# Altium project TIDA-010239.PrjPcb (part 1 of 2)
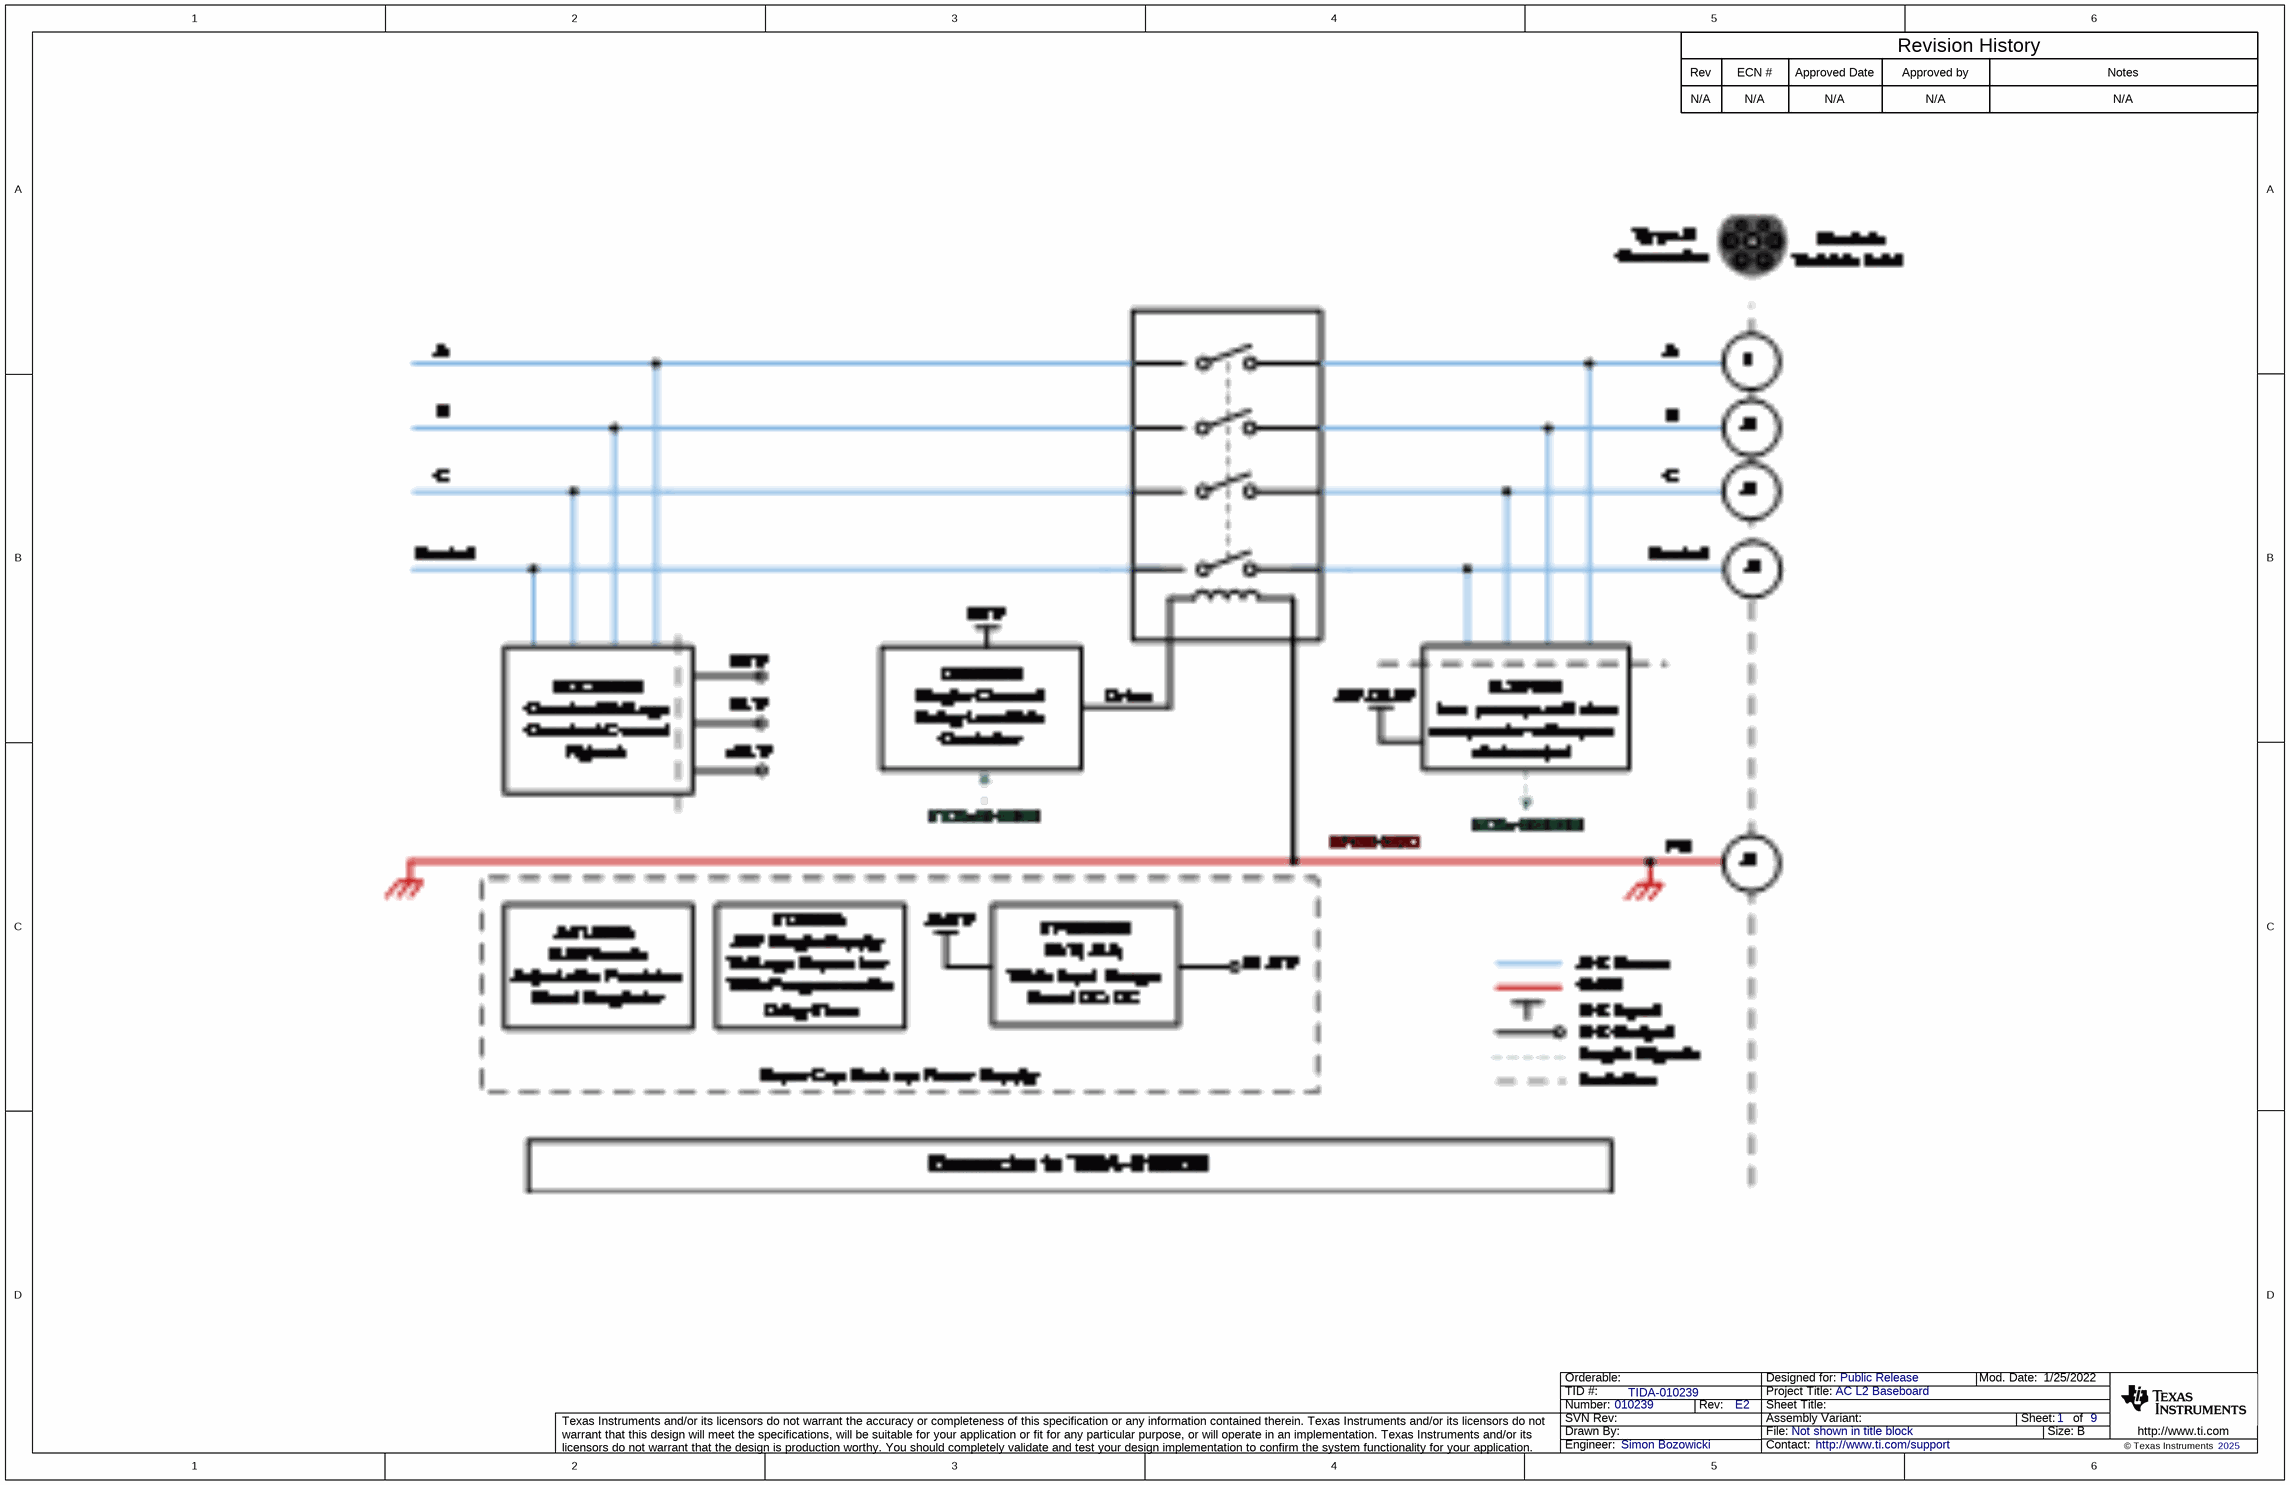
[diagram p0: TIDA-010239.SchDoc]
TID: TIDA-010239; TechSupport: http://www.ti.com/support; SCH_Rev: E2; PRJ_Title: AC L2 Baseboard; PRJ_Number: 010239; PRJ_Engineer: Simon Bozowicki; PRJ_Customer: Public Release; PCB_Rev: E2; PCB_Layout: Rich Chen; CopyrightYear: 2025
9 sheets, 300 parts. Net scope: flat (ports and power ports of the same name join across sheets).
Board file: TIDA-010239.PcbDoc
Sheets:
  TIDA-010239.SchDoc
  TIDA-010239_PWR_Flyback.SchDoc
  TIDA-010239_PWR_Backup.SchDoc
  TIDA-010239_Relay_DRV.SchDoc
  TIDA-010239_Weld_Detection.SchDoc
  TIDA-010239_Weld_Detection_B.SchDoc
  TIDA-010239_HPGP_ZC.SchDoc
  TIDA-010239_Connector.SchDoc
  TIDA-010239_Hardware.SchDoc

## Sheet TIDA-010239.SchDoc
size 431 x 279 mm; Date: Not shown in title block; ApprovedBy: Not shown in title block; CheckedBy: Not shown in title block; Author: Not shown in title block; CompanyName: Not shown in title block; Engineer: Not shown in title block; Organization: Not shown in title block; Address1: Not shown in title block; Address2: Not shown in title block; Address3: Not shown in title block; Address4: Not shown in title block; DocumentNumber: 1; Revision: Use project parameter SCH_Rev; SheetNumber: 1; SheetTotal: 9; PageSetup: Record=PageOptions¦CenterHorizontal=True¦CenterVertical=True¦PrintScale=1.00¦XCorrection=1.00¦YCorrection=1.00¦PrintKind=0¦BorderSize=5000000¦LeftOffset=0¦BottomOffset=0¦Orientation=2¦PaperLength=1000¦PaperWidth=1000¦Scale=100¦PaperSource=15¦PrintQuality=600¦MediaType=1¦DitherType=10¦PaperKind=Letter¦PrintScaleMode=1

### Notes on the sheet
- Rev
- N/A
- ECN #
- Approved Date
- Approved by
- Revision History
- Notes

## Sheet TIDA-010239_PWR_Flyback.SchDoc
size 431 x 279 mm; Date: Not shown in title block; ApprovedBy: Not shown in title block; CheckedBy: Not shown in title block; Author: Not shown in title block; CompanyName: Not shown in title block; Engineer: Not shown in title block; Organization: Not shown in title block; Address1: Not shown in title block; Address2: Not shown in title block; Address3: Not shown in title block; Address4: Not shown in title block; DocumentNumber: 1; Revision: Use project parameter SCH_Rev; SheetNumber: 2; SheetTotal: 9; PageSetup: Record=PageOptions¦CenterHorizontal=True¦CenterVertical=True¦PrintScale=1.00¦XCorrection=1.00¦YCorrection=1.00¦PrintKind=0¦BorderSize=5000000¦LeftOffset=0¦BottomOffset=0¦Orientation=2¦PaperLength=1000¦PaperWidth=1000¦Scale=100¦PaperSource=15¦PrintQuality=600¦MediaType=1¦DitherType=10¦PaperKind=Letter¦PrintScaleMode=1
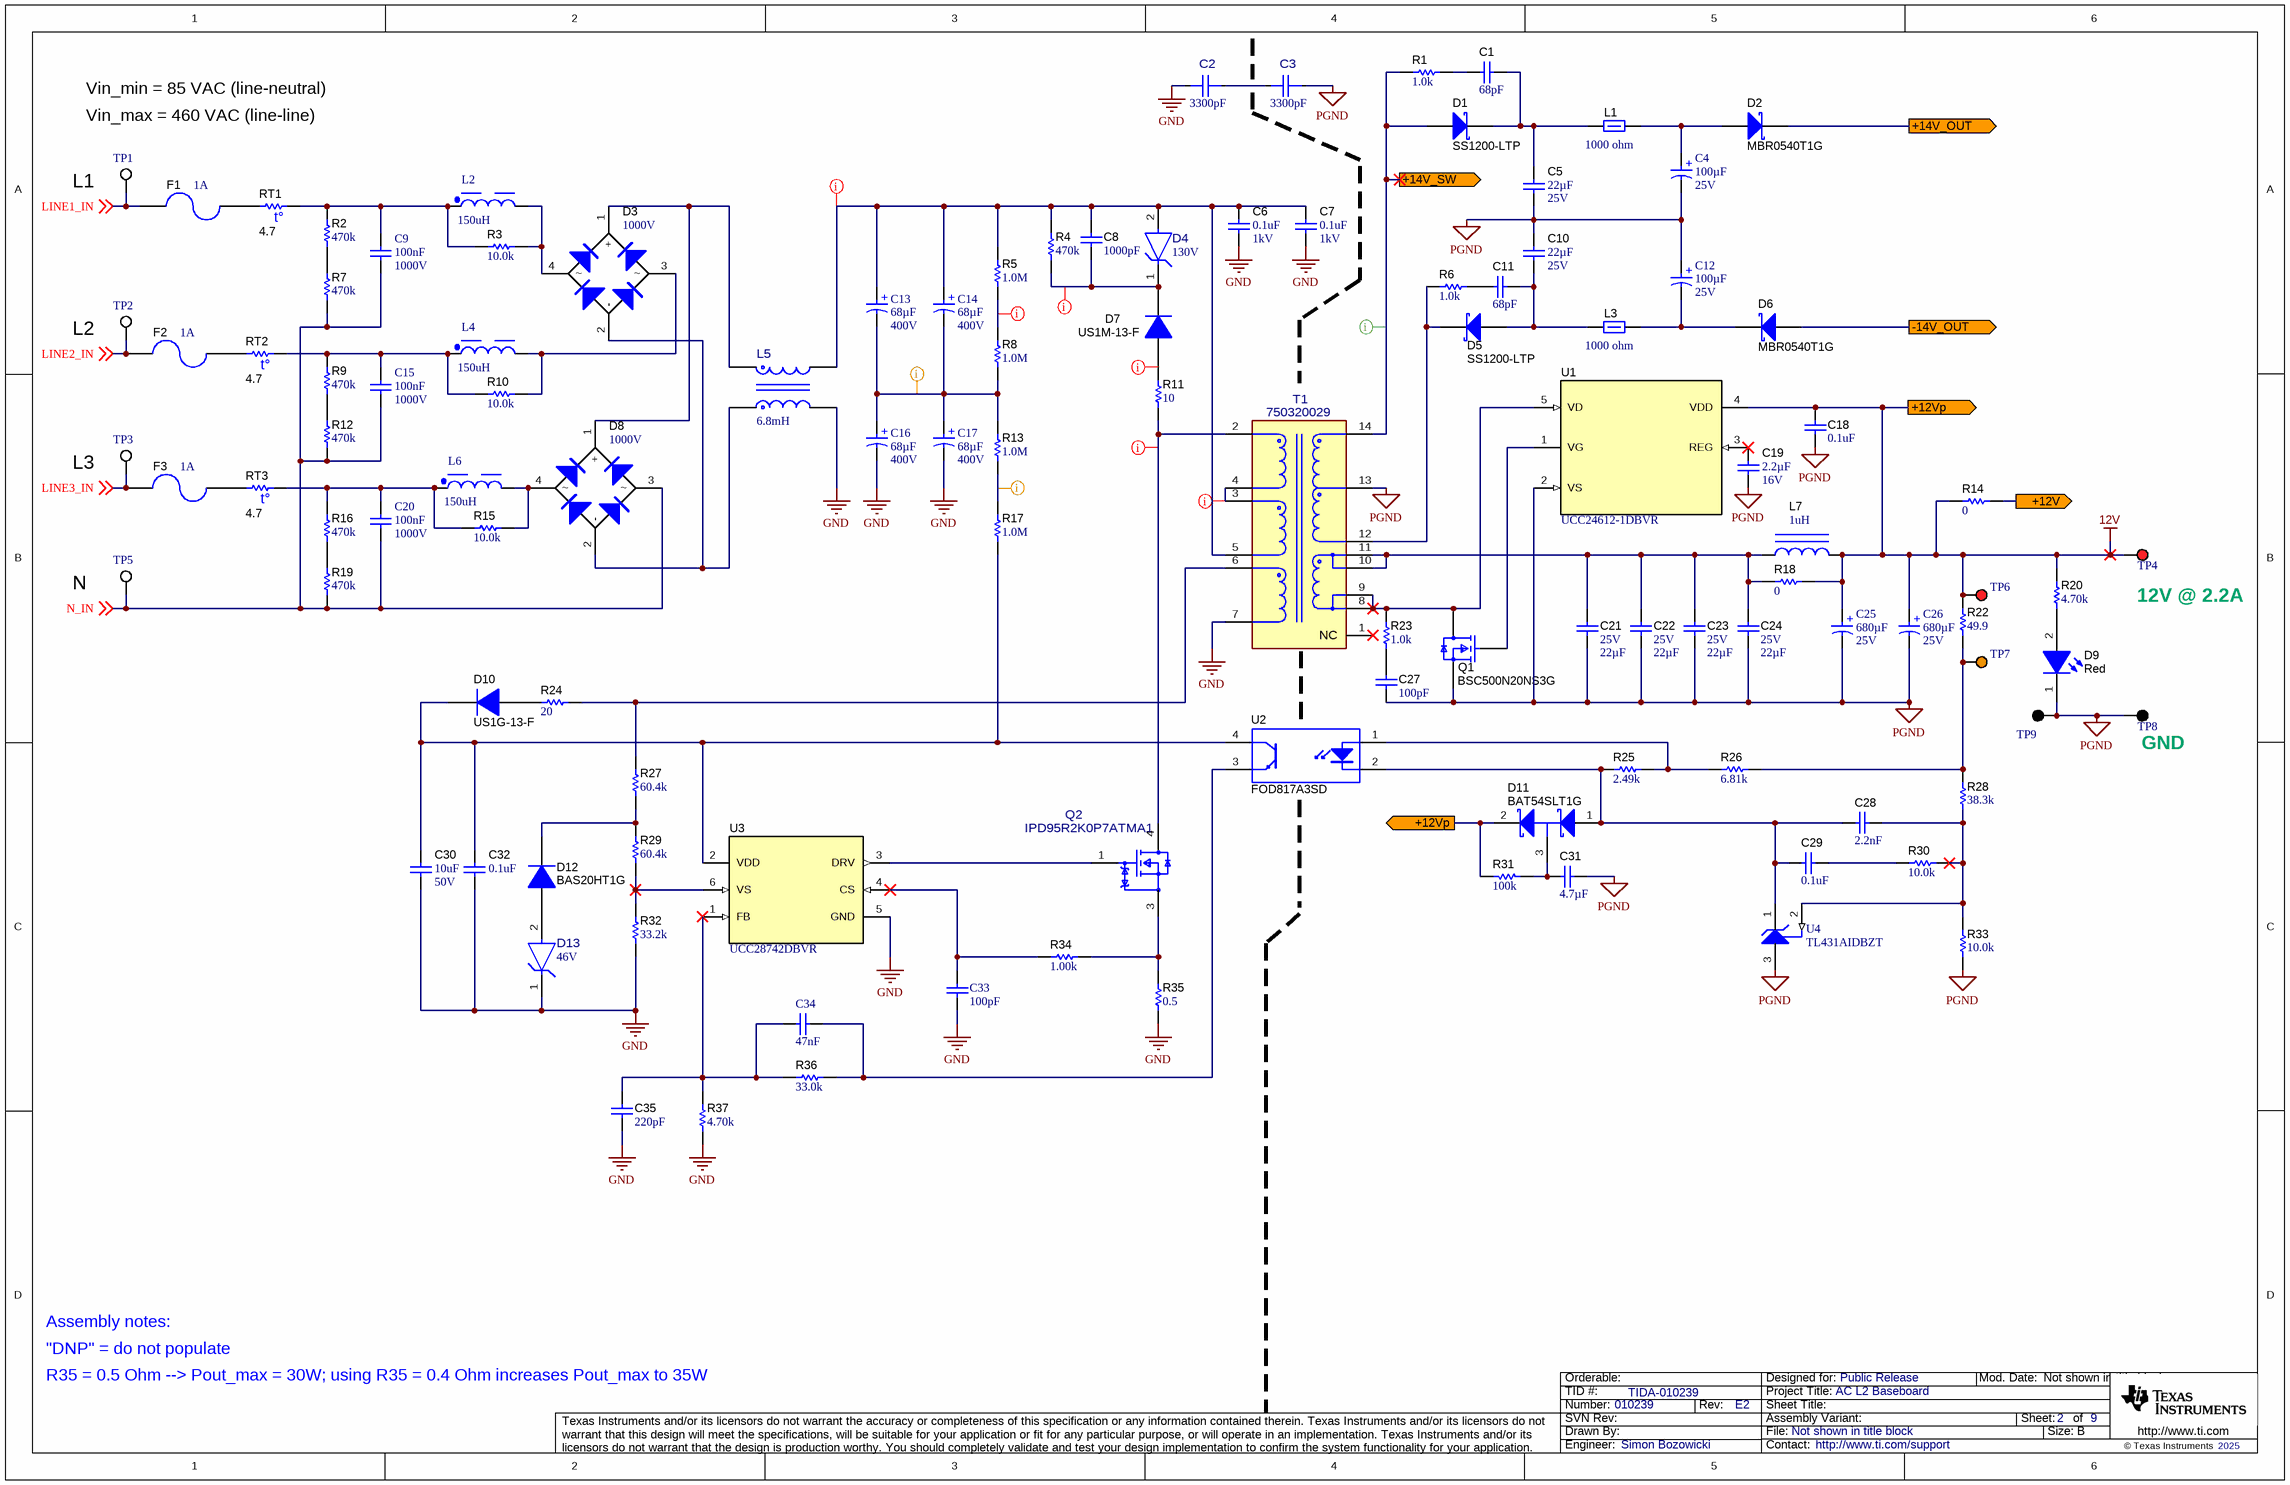
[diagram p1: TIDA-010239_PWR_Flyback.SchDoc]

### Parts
C1  ValueDisplayed: 68pF  [0805_HV]  (hidden comment: GRM21A5C2E680JW01D)
C2  ValueDisplayed: 3300pF  [FP-DE1E3RA332MN4AP01F_RADIAL_CAP_10MM0_5MM0_10MM0-MFG]  (hidden comment: DE1E3RA332MN4AP01F)
C3  ValueDisplayed: 3300pF  [FP-DE1E3RA332MN4AP01F_RADIAL_CAP_10MM0_5MM0_10MM0-MFG]  (hidden comment: DE1E3RA332MN4AP01F)
C4  value 100µF  Rated Voltage (DC): 25V  [WCAP-ATG8_D6.3H11]  (hidden comment: 860010473007)
C5  VDC_V: 25V  ValueDisplayed: 22µF  [1210_270]  (hidden comment: CC1210KKX7R8BB226)
C6  VDC_V: 1kV  ValueDisplayed: 0.1uF  [1812_254]  (hidden comment: C1812W104KDRACTU)
C7  VDC_V: 1kV  ValueDisplayed: 0.1uF  [1812_254]  (hidden comment: C1812W104KDRACTU)
C8  ValueDisplayed: 1000pF  [1206]  (hidden comment: VJ1206Y102KXEAT5Z)
C9  value 100nF  Rated Voltage (DC): 1000V  [WCAP-FTBE_L18W8.5H15]  (hidden comment: 890493425009CS)
C10  VDC_V: 25V  ValueDisplayed: 22µF  [1210_270]  (hidden comment: CC1210KKX7R8BB226)
C11  ValueDisplayed: 68pF  [0805_HV]  (hidden comment: GRM21A5C2E680JW01D)
C12  value 100µF  Rated Voltage (DC): 25V  [WCAP-ATG8_D6.3H11]  (hidden comment: 860010473007)
C13  value 68µF  Rated Voltage (DC): 400V  [WCAP-ATG5_D16H25]  (hidden comment: 860021380017)
C14  value 68µF  Rated Voltage (DC): 400V  [WCAP-ATG5_D16H25]  (hidden comment: 860021380017)
C15  value 100nF  Rated Voltage (DC): 1000V  [WCAP-FTBE_L18W8.5H15]  (hidden comment: 890493425009CS)
C16  value 68µF  Rated Voltage (DC): 400V  [WCAP-ATG5_D16H25]  (hidden comment: 860021380017)
C17  value 68µF  Rated Voltage (DC): 400V  [WCAP-ATG5_D16H25]  (hidden comment: 860021380017)
C18  value 0.1uF  [0603]  (hidden comment: C1608X7R1H104K080AA)
C19  VDC_V: 16V  Cap_F: 2.2µF  [0603]  (hidden comment: GRM188Z71C225KE43)
C20  value 100nF  Rated Voltage (DC): 1000V  [WCAP-FTBE_L18W8.5H15]  (hidden comment: 890493425009CS)
C21  VDC_V: 25V  ValueDisplayed: 22µF  [1210_270]  (hidden comment: CC1210KKX7R8BB226)
C22  VDC_V: 25V  ValueDisplayed: 22µF  [1210_270]  (hidden comment: CC1210KKX7R8BB226)
C23  VDC_V: 25V  ValueDisplayed: 22µF  [1210_270]  (hidden comment: CC1210KKX7R8BB226)
C24  VDC_V: 25V  ValueDisplayed: 22µF  [1210_270]  (hidden comment: CC1210KKX7R8BB226)
C25  value 680µF  Rated Voltage (DC): 25V  [WCAP-ATUL_D10H20]  (hidden comment: 860040475009)
C26  value 680µF  Rated Voltage (DC): 25V  [WCAP-ATUL_D10H20]  (hidden comment: 860040475009)
C27  ValueDisplayed: 100pF  [0805_HV]  (hidden comment: GRM21A5C2E101JW01D)
C28  Cap_F: 2.2nF  [0603]  (hidden comment: C0603C222K5RAC)
C29  value 0.1uF  [0603]  (hidden comment: C1608X7R1H104K080AA)
C30  VDC_V: 50V  ValueDisplayed: 10uF  [1206_180]  (hidden comment: CL31B106KBHNNNE)
C31  Cap_F: 4.7µF  [0805_HV]  (hidden comment: C2012X7R1E475K125AB)
C32  value 0.1uF  [0603]  (hidden comment: C1608X7R1H104K080AA)
C33  value 100pF  [WCAP-CSGP_0603_L1.6W0.8H0.8_Reflow]  (hidden comment: 885012006057)
C34  value 47nF  [WCAP-CSGP_0603_L1.6W0.8H0.8_Reflow]  (hidden comment: 885012206093)
C35  ValueDisplayed: 220pF  [0603]  (hidden comment: C0603C221J5GACTU)
D1  SS1200-LTP  [SMA]
D2  MBR0540T1G  [SOD-123]
D3  value 1000V  [TBS4]  (hidden comment: TBS22M-TP)
D4  VRWM: 130V  [FP-SMCJ130A_DO-214AB-MFG]  (hidden comment: SMCJ130A)
D5  SS1200-LTP  [SMA]
D6  MBR0540T1G  [SOD-123]
D7  US1M-13-F  [SMA]
D8  value 1000V  [TBS4]  (hidden comment: TBS22M-TP)
D9  value Red  [WL_SMCW_RED_1206]  (hidden comment: 150120RS75000)
D10  US1G-13-F  [SMA]
D11  BAT54SLT1G  [SOT-23]
D12  BAS20HT1G  [SOD-323]
D13  Vf_V: 46V  [FP-BZX384C43-E3-08_SOD323-MFG]  (hidden comment: BZX384C43-E3-08)
F1  Irating_A: 1A  [FUSE_0443]  (hidden comment: 0443001.DR)
F2  Irating_A: 1A  [FUSE_0443]  (hidden comment: 0443001.DR)
F3  Irating_A: 1A  [FUSE_0443]  (hidden comment: 0443001.DR)
L1  value 1000 ohm  [0805_HV]  (hidden comment: 74279205)
L2  value 150uH  [WE-TI_1014]  (hidden comment: 7447480151)
L3  value 1000 ohm  [0805_HV]  (hidden comment: 74279205)
L4  value 150uH  [WE-TI_1014]  (hidden comment: 7447480151)
L5  value 6.8mH  [FP-7446121007_PTH_CMC_18MM5_13MM5-MFG]  (hidden comment: 7446121007)
L6  value 150uH  [WE-TI_1014]  (hidden comment: 7447480151)
L7  ValueDisplayed: 1uH  [WE-PD2-S]  (hidden comment: 7447730)
Q1  BSC500N20NS3G  [FP-BSC220N20NSFDATMA1_TSON-8-MFG]
Q2  IPD95R2K0P7ATMA1  [FP-IPD95R2K0P7ATMA1_DPAK-MFG]
R1  ValueDisplayed: 1.0k  [0805_HV]  (hidden comment: ERJ-6GEYJ102V)
R2  ValueDisplayed: 470k  [1206]  (hidden comment: CRCW1206470KJNEA)
R3  ValueDisplayed: 10.0k  [0805_HV]  (hidden comment: CRCW080510K0FKEA)
R4  ValueDisplayed: 470k  [1206]  (hidden comment: CRCW1206470KJNEA)
R5  ValueDisplayed: 1.0M  [1206]  (hidden comment: CRCW12061M00JNEA)
R6  ValueDisplayed: 1.0k  [0805_HV]  (hidden comment: ERJ-6GEYJ102V)
R7  ValueDisplayed: 470k  [1206]  (hidden comment: CRCW1206470KJNEA)
R8  ValueDisplayed: 1.0M  [1206]  (hidden comment: CRCW12061M00JNEA)
R9  ValueDisplayed: 470k  [1206]  (hidden comment: CRCW1206470KJNEA)
R10  ValueDisplayed: 10.0k  [0805_HV]  (hidden comment: CRCW080510K0FKEA)
R11  ValueDisplayed: 10  [1206]  (hidden comment: CRCW120610R0JNEA)
R12  ValueDisplayed: 470k  [1206]  (hidden comment: CRCW1206470KJNEA)
R13  ValueDisplayed: 1.0M  [1206]  (hidden comment: CRCW12061M00JNEA)
R14  ValueDisplayed: 0  [1206]  (hidden comment: RC1206JR-070RL)
R15  ValueDisplayed: 10.0k  [0805_HV]  (hidden comment: CRCW080510K0FKEA)
R16  ValueDisplayed: 470k  [1206]  (hidden comment: CRCW1206470KJNEA)
R17  ValueDisplayed: 1.0M  [1206]  (hidden comment: CRCW12061M00JNEA)
R18  ValueDisplayed: 0  [1206]  (hidden comment: RC1206JR-070RL)
R19  ValueDisplayed: 470k  [1206]  (hidden comment: CRCW1206470KJNEA)
R20  ValueDisplayed: 4.70k  [0603]  (hidden comment: RC0603FR-074K7L)
R22  ValueDisplayed: 49.9  [0603]  (hidden comment: CRCW060349R9FKEA)
R23  ValueDisplayed: 1.0k  [1206]  (hidden comment: CRCW12061K00JNEA)
R24  ValueDisplayed: 20  [0805_HV]  (hidden comment: CRCW080520R0JNEA)
R25  ValueDisplayed: 2.49k  [0603]  (hidden comment: CRCW06032K49FKEA)
R26  ValueDisplayed: 6.81k  [0603]  (hidden comment: CRCW06036K81FKEA)
R27  ValueDisplayed: 60.4k  [0805_HV]  (hidden comment: ERJ-6ENF6042V)
R28  ValueDisplayed: 38.3k  [0603]  (hidden comment: RC0603FR-0738K3L)
R29  ValueDisplayed: 60.4k  [0805_HV]  (hidden comment: ERJ-6ENF6042V)
R30  ValueDisplayed: 10.0k  [0603]  (hidden comment: RC0603FR-0710KL)
R31  ValueDisplayed: 100k  [0603]  (hidden comment: CRCW0603100KFKEA)
R32  ValueDisplayed: 33.2k  [0603]  (hidden comment: RC0603FR-0733K2L)
R33  ValueDisplayed: 10.0k  [0603]  (hidden comment: RC0603FR-0710KL)
R34  ValueDisplayed: 1.00k  [0603]  (hidden comment: CRCW06031K00FKEA)
R35  ValueDisplayed: 0.5  [2010]  (hidden comment: CSRN2010FKR500)
R36  ValueDisplayed: 33.0k  [0603]  (hidden comment: RC0603FR-0733KL)
R37  ValueDisplayed: 4.70k  [0603]  (hidden comment: RC0603FR-074K7L)
RT1  value 4.7  [S153]  (hidden comment: B57153S0479M051)
RT2  value 4.7  [S153]  (hidden comment: B57153S0479M051)
RT3  value 4.7  [S153]  (hidden comment: B57153S0479M051)
T1  750320029  [FP-750320029_PTH14_32MM25_27MM05-MFG]
TP1  5012  [Keystone5012]  (value not drawn)
TP2  5012  [Keystone5012]  (value not drawn)
TP3  5012  [Keystone5012]  (value not drawn)
TP4  5010  [Keystone5010]  (value not drawn)
TP5  5012  [Keystone5012]  (value not drawn)
TP6  5000  [Keystone5000]  (value not drawn)
TP7  5003  [Keystone5003]  (value not drawn)
TP8  5011  [Keystone5011]  (value not drawn)
TP9  5001  [Keystone5001]  (value not drawn)
U1  UCC24612-1DBVR  [DBV0005A_N]
U2  FOD817A3SD  [N04C]
U3  UCC28742DBVR  [DBV0006A_N]
U4  TL431AIDBZT  [DBZ0003A_N]

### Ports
+12V (out), +12Vp (out), +14V_OUT (out), +14V_SW (out), -14V_OUT (out)

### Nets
12V: C18.1 C25.1(P) C26.1(P) D11.2(K) L7.2 R14.1 R18.2 R20.2 R22.2 R31.1 TP4.1 TP6.1 U1.4(VDD) ; port +12Vp
GND: C2.2 C6.2 C7.2 C16.2(N) C17.2(N) C30.2 C32.2 C33.2 C35.1 D13.1(CATHODE) L5.3 R32.1 R35.1 R37.1 T1.7 U3.5(GND)
PGND: C3.1 C4.2(N) C5.2 C10.1 C12.1(P) C18.2 C19.2 C21.1 C22.1 C23.1 C24.1 C25.2(N) C26.2(N) C27.2 C31.2 D9.1(K) Q1.1-2-3(S) R33.1 T1.13 TP8.1 TP9.1 U1.2(VS) U4.3(ANODE)
+12V: R14.2 ; port +12V
+14V_OUT: D2.1(K) ; port +14V_OUT
+14V_SW: D1.2(A) R1.1 T1.14 ; port +14V_SW
-14V_OUT: D6.2(A) ; port -14V_OUT
LINE1_IN: F1.2 TP1.1 ; off-sheet LINE1_IN
LINE2_IN: F2.2 TP2.1 ; off-sheet LINE2_IN
LINE3_IN: F3.2 TP3.1 ; off-sheet LINE3_IN
N_IN: C9.2 C15.2 C20.2 D8.3 R7.1 R12.1 R19.1 TP5.1 ; off-sheet N_IN
NetC1_1: C1.1 C5.1 D1.1(K) L1.1
NetC1_2: C1.2 R1.2
NetC2_1: C2.1 C3.2
NetC4_1: C4.1(P) D2.2(A) L1.2
NetC6_1: C6.1 C7.1 C8.1 C13.1(P) C14.1(P) D4.2(ANODE) L5.4 R4.2 R5.2 T1.5
NetC8_2: C8.2 D4.1(CATHODE) D7.1(K) R4.1
NetC9_1: C9.1 L2.1 R2.2 R3.1 RT1.2
NetC10_2: C10.2 C11.1 D5.2(A) L3.1
NetC11_2: C11.2 R6.2
NetC12_2: C12.2(N) D6.1(K) L3.2
NetC13_2: C13.2(N) C14.2(N) C16.1(P) C17.1(P) R8.1 R13.2
NetC15_1: C15.1 L4.1 R9.2 R10.1 RT2.2
NetC19_1: C19.1 U1.3(REG)
NetC20_1: C20.1 L6.1 R15.1 R16.2 RT3.2
NetC21_2: C21.2 C22.2 C23.2 C24.2 L7.1 R18.1 T1.10 T1.11
NetC27_1: C27.1 R23.1
NetC28_1: C28.1 C29.1 D11.1(A) R25.2 U2.2(K) U4.1(CATHODE)
NetC28_2: C28.2 R28.1 R30.2 R33.2 U4.2(REF)
NetC29_2: C29.2 R30.1
NetC30_1: C30.1 C32.1 D10.1(K) R17.1 U2.4(C) U3.2(VDD)
NetC31_1: C31.1 D11.3(C) R31.2
NetC33_1: C33.1 R34.1 U3.4(CS)
NetC34_1: C34.1 R36.2 U2.3(E)
NetC34_2: C34.2 C35.2 R36.1 R37.2 U3.1(FB)
NetD3_1: D3.1(+) D8.1(+) L5.1
NetD3_2: D3.2(-) D8.2(-) L5.2
NetD3_3: D3.3 L4.2 R10.2
NetD3_4: D3.4 L2.2 R3.2
NetD5_1: D5.1(K) R6.1 T1.12
NetD7_2: D7.2(A) R11.2
NetD8_4: D8.4 L6.2 R15.2
NetD9_2: D9.2(A) R20.1
NetD10_2: D10.2(A) R24.1
NetD12_1: D12.1(K) R27.1 R29.2
NetD12_2: D12.2(A) D13.2(ANODE)
NetF1_1: F1.1 RT1.1
NetF2_1: F2.1 RT2.1
NetF3_1: F3.1 RT3.1
NetQ1_4: Q1.4(G) U1.1(VG)
NetQ1_5-6-7-8: Q1.5-6-7-8(D) R23.2 T1.8 T1.9 U1.5(VD)
NetQ2_1: Q2.1(Gate) U3.3(DRV)
NetQ2_3: Q2.3(Source) R34.2 R35.2
NetQ2_4: Q2.4(Drain) R11.1 T1.2
NetR2_1: R2.1 R7.2
NetR5_1: R5.1 R8.2
NetR9_1: R9.1 R12.2
NetR13_1: R13.1 R17.2
NetR16_1: R16.1 R19.2
NetR22_1: R22.1 R26.2 R28.2 TP7.1
NetR24_2: R24.2 R27.2 T1.6
NetR25_1: R25.1 R26.1 U2.1(A)
NetR29_1: R29.1 R32.2 U3.6(VS)
NetT1_3: T1.3 T1.4

Not connected (* = marked no-connect by the designer): T1 1(NC)*

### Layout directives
rule Clearance Constraint [Clearance = 40mil]: NetC6_1, NetC8_2, NetD7_2, NetQ2_4, NetR5_1, NetT1_3
rule Clearance Constraint [Clearance = 20mil]: NetC13_2, NetR13_1
rule Clearance Constraint [Clearance = 10mil]: +14V_SW

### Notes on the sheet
- Vin_min = 85 VAC (line-neutral)
- Vin_max = 460 VAC (line-line)
- (near TP1) L1
- (near TP2) L2
- (near TP3) L3
- (near TP5) N
- (near TP4) 12V @ 2.2A
- (near TP8) GND
- Assembly notes:
- "DNP" = do not populate
- R35 = 0.5 Ohm --> Pout_max = 30W; using R35 = 0.4 Ohm increases Pout_max to 35W

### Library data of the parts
C1 C11 = CMP-0008246-2: CAP, CERM, 68 pF, 250 V, +/- 5%, C0G/NP0, 0805; Manufacturer: MuRata; TaMin_C: -55°C; Polarized: N; SizeAreaWB_mm2: 6.75; Value1: Unknown; U/M: EA; Value: 68pF; TaMax_C: 125°C; SizeZ_mm: 1.45; SizeX_mm: 2; SizeY_mm: 1.25; Cap_Case: 0805; Value2: 250V; SizeArea_mm2: 2.5; AEC Category: Q200
C2 C3 = CMP-0127096-1: Cap Ceramic Disc 3300pF 20% 300VAC Thru-Hole 10.0x5.0x10.0 Ammo pack; Manufacturer: Murata; AEC Qualified: No; Cap_F: 3.3nF; SizeZ_mm: 13mm; TempCo: +20/-55%; VAC: 300V; Temperature Characteristic: E; Value: 3.3nF; Voltage Ac Rating X: 440V
C4 C12 = CMP-0116473-1: WCAP-ATG8 Aluminum Electrolytic Capacitor, Radial, THT, D6.3 x H11mm, 100uF, 25V; Manufacturer: Wurth Elektronik; Capacitance Tolerance: +/-20%; Dissipation Factor: 14%; Endurance: 2000h; Leakage Current: 25uA; Ripple Current: 209mA; Technical Reference: ATBD110101M025DSPA4B000
C5 C10 C21-C24 = CMP-0082267-1: CAP, CERM, 22 µF, 25 V,+/- 10%, X7R, 1210; Manufacturer: Yageo; TaMin_C: -55°C; ESR_ohm: 1m; Polarized: N; SizeAreaWB_mm2: 14.7; Value1: 0.001 ohm; U/M: EA; Value: 22uF; TaMax_C: 125°C; SizeZ_mm: 2.7; SizeX_mm: 3.2; SizeY_mm: 2.5; Cap_Case: 1210; SizeArea_mm2: 8; AEC Category: Q200
C6 C7 = CMP-0009326-2: CAP, CERM, 0.1 uF, 1000 V, +/- 10%, X7R, 1812; Manufacturer: Kemet; TaMin_C: -55°C; Polarized: N; SizeAreaWB_mm2: 23.1; Value1: Unknown; U/M: EA; Value: 0.1uF; TaMax_C: 125°C; SizeZ_mm: 2.54; SizeX_mm: 4.5; SizeY_mm: 3.2; Cap_Case: 1812; Value2: 1000V; SizeArea_mm2: 14.4; Cap_F: 100nF; AEC Category: Q200
C8 = CMP-0009039-2: CAP, CERM, 1000 pF, 500 V, +/- 10%, X7R, 1206; Manufacturer: Vishay-Vitramon; TaMin_C: -55°C; Polarized: N; SizeAreaWB_mm2: 10.92; Value1: Unknown; U/M: EA; Value: 1000pF; TaMax_C: 125°C; SizeZ_mm: 1.35; SizeX_mm: 3.2; SizeY_mm: 1.6; Value2: 500V; SizeArea_mm2: 5.12; Cap_F: 1nF; AEC Category: Q200
C9 C15 C20 = CMP-0105615-1: WCAP-FTBE Film Capacitor, THT, L18 x W8.5 x H15mm, 100nF, 1000V; Manufacturer: Wurth Elektronik; Capacitance Tolerance: +/-10%; Technical Reference: MPSP015104KA00DCPP45004; Dissipation Factor @100kHz: 2.5%; Dissipation Factor @10kHz: 1.4%; Dissipation Factor @1kHz: 1%; Insulation Resistance: 9000MOhm; Pitch: 15mm; Rate of Voltage Rise: 44V/us
C13 C14 C16 C17 = CMP-0102466-1: WCAP-ATG5 Aluminum Electrolytic Capacitor, Radial, THT, D16 x H25mm, 68µF, 400V; Manufacturer: Wurth Elektronik; Capacitance Tolerance: +/-20%; Dissipation Factor: 15%; Endurance: 2000h; Leakage Current: 816uA; Ripple Current: 410mA; Technical Reference: ATJK250680M400DSPAEB000
C18 C29 C32 = CMP-0007044-5: CAP, CERM, 0.1 uF, 50 V, +/- 10%, X7R, 0603; Manufacturer: TDK; TaMin_C: -55°C; ESR_ohm: 29.6m; Polarized: N; SizeAreaWB_mm2: 4.68; Value1: 0.0296 ohm; U/M: EA; TaMax_C: 125°C; SizeZ_mm: 1; SizeX_mm: 1.6; SizeY_mm: 0.8; Value2: 50V; SizeArea_mm2: 1.28; Cap_F: 100nF; IRMS_A: 971.99mA; AEC Category: Q200
C19 = CMP-0007499-4: CAP, CERM, 2.2 uF, 16 V, +/- 10%, X7R, 0603; Manufacturer: MuRata; TaMin_C: -55°C; Polarized: N; SizeAreaWB_mm2: 4.68; Value1: Unknown; U/M: EA; Value: 2.2uF; TaMax_C: 125°C; SizeZ_mm: 1; SizeX_mm: 1.6; SizeY_mm: 0.8; SizeArea_mm2: 1.28; AEC Category: Q200
C25 C26 = CMP-0116844-1: WCAP-ATUL Aluminum Electrolytic Capacitor, Radial, THT, D10 x H20mm, 680µF, 25V; Manufacturer: Wurth Elektronik; Capacitance Tolerance: 20%; Dissipation Factor: 14%; Endurance: 7000h; Leakage Current: 170uA; Ripple Current: 1400mA; Technical Reference: ATDF200681M025DSPAAG000
C27 = CMP-0008236-2: CAP, CERM, 100 pF, 250 V, +/- 5%, C0G/NP0, 0805; Manufacturer: MuRata; TaMin_C: -55°C; Polarized: N; SizeAreaWB_mm2: 6.75; Value1: Unknown; U/M: EA; Value: 100pF; TaMax_C: 125°C; SizeZ_mm: 1.45; SizeX_mm: 2; SizeY_mm: 1.25; Cap_Case: 0805; Value2: 250V; SizeArea_mm2: 2.5; AEC Category: Q200
C28 = CMP-0006897-4: CAP, CERM, 2200 pF, 50 V, +/- 10%, X7R, 0603; Manufacturer: Kemet; TaMin_C: -55°C; Polarized: N; SizeAreaWB_mm2: 4.68; Value1: Unknown; U/M: EA; Value: 2200pF; TaMax_C: 125°C; SizeZ_mm: 1; SizeX_mm: 1.6; SizeY_mm: 0.8; Value2: 50V; SizeArea_mm2: 1.28; AEC Category: Q200
C30 = CMP-0008802-2: CAP, CERM, 10 uF, 50 V, +/- 10%, X7R, 1206; Manufacturer: Samsung; TaMin_C: -55°C; Polarized: N; SizeAreaWB_mm2: 10.92; Value1: Unknown; U/M: EA; Value: 10uF; TaMax_C: 125°C; SizeZ_mm: 1.8; SizeX_mm: 3.2; SizeY_mm: 1.6; Cap_Case: 1206; SizeArea_mm2: 5.12; Cap_F: 10µF; AEC Category: Q200
C31 = CMP-0007870-2: CAP, CERM, 4.7 uF, 25 V, +/- 10%, X7R, 0805; Manufacturer: TDK; TaMin_C: -55°C; Polarized: N; SizeAreaWB_mm2: 6.75; Value1: Unknown; U/M: EA; Value: 4.7uF; TaMax_C: 125°C; SizeZ_mm: 1.45; SizeX_mm: 2; SizeY_mm: 1.25; Cap_Case: 0805; Value2: 25V; SizeArea_mm2: 2.5; AEC Category: Q200
C33 = CMP-0118889-1: WCAP-CSGP Multilayer Ceramic Chip Capacitor, General Purpose, size 0603, NP0, 100pF, 50VDC; Manufacturer: Wurth Elektronik; Capacitance Tolerance: +/-5%; Insulation Resistance: 10GOhm; Q Factor: 1000; Rated Voltage (DC): 50V; Technical Reference: NP00603101J050DFCT10000
C34 = CMP-0115476-1: WCAP-CSGP Multilayer Ceramic Chip Capacitor, General Purpose, size 0603, X7R, 47nF, 50VDC; Manufacturer: Wurth Elektronik; Capacitance Tolerance: +/-10%; Dissipation Factor: 3%; Insulation Resistance: 10GOhm; Rated Voltage (DC): 50V; Technical Reference: X7R0603473K050DFCT10000
C35 = CMP-0006893-4: CAP, CERM, 220 pF, 50 V, +/- 5%, C0G/NP0, 0603; Manufacturer: Kemet; TaMin_C: -55°C; Polarized: N; SizeAreaWB_mm2: 4.68; Value1: Unknown; U/M: EA; Value: 220pF; TaMax_C: 125°C; SizeZ_mm: 1; SizeX_mm: 1.6; SizeY_mm: 0.8; Value2: 50V; SizeArea_mm2: 1.28; AEC Category: Q200
D1 D5 = CMP-0028981-2: Diode, Schottky, 200 V, 1 A, SMA; Manufacturer: Micro Commercial Components; TJmax_C: 150°C; SizeArea_mm2: 16.3228; Io_A: 1A; AEC Qualified: N; SizeX_mm: 5.59; SizeZ_mm: 2.87; Vf_V: 920mV; Value: 200V; AEC Category: Q101; Value2: 0.92V; SizeY_mm: 2.92; SizeAreaWB_mm2: 37.3428
D2 D6 = CMP-0028526-2: Diode, Schottky, 40 V, 0.5 A, SOD-123; Manufacturer: ON Semiconductor; Green_REACh: Passed; SizeY_mm: 1.7; Io_A: 500mA; SizeArea_mm2: 6.545; RJC_CperW: 118; Green_Lifecycle: Active; Vr_V: 40V; Vf_V: 510mV; TJmax_C: 150°C; AEC Category: Q101; SizeAreaWB_mm2: 13.095; Value1: 0.5A; SizeZ_mm: 1.35; SizeX_mm: 3.85; Value2: 0.51V; Value: 40V
D3 D8 = CMP-0029252-3: Diode, Switching-Bridge, 1000 V, 2.2 A, 8.25x6.6mm; Manufacturer: Micro Commercial Components; Io_A: 2.2A; SizeAreaWB_mm2: 88.15; Vr_V: 1kV; TJmax_C: 150°C; SizeZ_mm: 1.5; SizeX_mm: 8.25; SizeY_mm: 6.6; Vf_V: 1.1V; SizeArea_mm2: 54.45; AEC Qualified: N; AEC Category: Q101; RJC_CperW: 10
D4 = CMP-0127069-1: 209V Clamp 7.2A Ipp Tvs Diode Surface Mount DO-214AB (SMCJ); Manufacturer: Littelfuse Inc; AEC Qualified: No; SizeZ_mm: 2.62mm; Ppk: 1.5kW; Breakdown Voltage: 144V; Direction: Unidirectional; Number Of Channels: 1; TJmax_C: +150°C
D7 = CMP-0076882-2: Diode, Ultrafast, 1000 V, 1 A, SMA; Manufacturer: Diodes Inc.; SizeAreaWB_mm2: 37.3428; Vr_V: 1kV; SizeArea_mm2: 16.3228; TJmax_C: 150°C; AEC Category: Q101; Value: 1000V; SizeZ_mm: 2.87; Green_REACh: Incomplete; Io_A: 1A; Vf_V: 1.7V; SizeY_mm: 2.92; Green_Lifecycle: Not Set; SizeX_mm: 5.59; RJC_CperW: 30.0
D9 = CMP-0002935-3: LED, Red, SMD; Manufacturer: Wurth Elektronik; Vf_V: 2V; Angle: 140; Value1: 0.072W; Vr_V: 5V; Io_A: 20mA; Tjmax_C: 85°C; Type: AlInGaP; Power_TotalModule: 72mW; Ir_A: 10µA
D10 = CMP-0077026-2: Diode, Ultrafast, 400 V, 1 A, SMA; Manufacturer: Diodes Inc.; Value: 400V; SizeY_mm: 2.92; Value1: 1A; SizeAreaWB_mm2: 37.3428; Value2: 1.3V; TJmax_C: 150°C; Green_REACh: Incomplete; SizeArea_mm2: 16.3228; SizeX_mm: 5.59; SizeZ_mm: 2.87; AEC Category: Q101; Green_Lifecycle: Not Set
D11 = CMP-0028613-2: Diode, Schottky, 30 V, 0.2 A, SOT-23; Manufacturer: ON Semiconductor; TJmax_C: 150°C; AEC Category: Q101; SizeAreaWB_mm2: 14; Value2: 0.8V; Value1: 0.2A; SizeZ_mm: 1.1; Value: 30V; Vf_V: 800mV; Green_Lifecycle: Not Set; Io_A: 200mA; SizeY_mm: 3; SizeX_mm: 2.5; SizeArea_mm2: 7.5; Green_REACh: Incomplete
D12 = CMP-0029150-2: Diode, Switching, 200 V, 0.2 A, AEC-Q101, SOD-323; Manufacturer: ON Semiconductor; Value2: 1.25V; Value1: 0.2A; SizeZ_mm: 1; Green_REACh: Incomplete; SizeArea_mm2: 3.645; Vr_V: 200V; SizeX_mm: 2.7; TJmax_C: 150°C; Io_A: 200mA; Value: 200V; Green_Lifecycle: Not Set; SizeAreaWB_mm2: 8.695; AEC Qualified: Y; AEC Category: Q101; SizeY_mm: 1.35
D13 = CMP-0124335-1: Diode Zener Single 43V ±5% 200mW 2-Pin SOD-323 T/R; Manufacturer: Vishay; AEC Qualified: No; SizeZ_mm: 1.15mm; TJmax_C: 150°C; Vr_V: 30.1V; Max Reverse Leakage Current: 0.05uA; Zener Impedance: 45Ω
F1-F3 = CMP-0003467-2: Fuse, 1 A, 250VAC/VDC, SMD; Manufacturer: Littelfuse; Interrupt_AC: 50A; Interrupt_DC: 250A; VAC_V: 250V; Rtyp_Ohm: 0.18; MeltingTyp: 10.17
L1 L3 = CMP-0003090-1: Ferrite Bead, 1000 ohm @ 100 MHz, 0.2 A, 0805; Manufacturer: Wurth Elektronik; Ztyp@1GHz_Ohm: 194.226; ZTyp@100MHz_Ohm: 1k; SizeAreaWB_mm2: 6.75; DCR_ohm: 0.45; Value1: 0.45 ohm; Imax_A: 200mA; SizeZ_mm: 1.45; SizeX_mm: 2; SizeY_mm: 1.25; Value2: 0.2A; SizeArea_mm2: 2.5
L2 L4 L6 = CMP-0099585-1: WE-TI Radial Leaded Wire Wound Inductor, size 1014, 150uH, 2A, 0.18Ohm; Manufacturer: Wurth Elektronik; DC Resistance: 0.16Ohm; Saturation Current: 2.1A; Self Resonant Frequency: 3.1MHz
L5 = CMP-0124348-1: 6.8 mH @ 10 kHz 2 Line Common Mode Choke Through Hole 1A DCR 300mOhm; Manufacturer: Wurth Electronics; DCR_ohm: 0.3; SizeZ_mm: 20.5mm; AEC Qualified: No; Ciiva Ids: 2520274; Import Ts: 1521862282; Test Frequency: 10kHz; Tolerance_%: 30%
L7 = CMP-0064228-1: Inductor, Shielded Drum Core, Ferrite, 1 uH, 4 A, 0.049 ohm, SMD; Manufacturer: Wurth Elektronik; Isat: 5.72A @ 10% inductance drop; Irms: 4A @ 40C rise; Green_Lifecycle: Active; SizeAreaWB_mm2: 27.5; DCR_ohm: 49m; Green_REACh: Passed; Value: 1uH; Imax_A: 4A; SizeZ_mm: 3.2; SizeX_mm: 4; SizeY_mm: 4.5; SizeArea_mm2: 18; Ind_H: 1µH; AEC Category: Q200
Q1 = CMP-0089849-1: Mosfet, N-Ch, 200V, 24A, 150Deg C Rohs Compliant: Yes; Manufacturer: Infineon; VdsMax_V: 1.2V; Threshold Vgs Min: 2V; Pulse Drain Current: 97A; QgTyp_nC: 15nC @ 10V; Transconductance: 88S; Vgs_V: 20V; Turn On Delay Time: 7ns; Rthja Max: 75K/W; Threshold Vgs Max: 4V; ChMode: False; Turn Off Delay Time: 28ns; Number Of Channels: 1; AEC Qualified: No; Rdson45_ohm: 42m; Typ Forward Diode Voltage: 1V; Input Capacitace At Vds: 2770pF @ 100V; SizeZ_mm: 1.1mm; TJmax_C: +175°C
Q2 = CMP-0091039-1: Trans MOSFET N-CH 950V 4A 3-Pin(2+Tab) DPAK T/R; Manufacturer: Infineon Technologies; Input Capacitace At Vds: 330pF @ 400V; TJmax_C: +150°C; Turn On Delay Time: 6ns; Turn Off Delay Time: 41ns; Number Of Channels: 1; Rthja Max: 62°C/W; AEC Qualified: No; QgTyp_nC: 10nC @ 10V; Reverse Recovery Charge: 2000nC; Pulse Drain Current: 10A; Power_W: 37W; Typ Forward Diode Voltage: 0.9V; SizeZ_mm: 2.48mm; Threshold Vgs Min: 2.5V; ChMode: False; Reverse Recovery Time: 337ns; Rdson45_ohm: 1.71; Threshold Vgs Max: 3.5V; Vgs_V: 20V
R1 R6 = CMP-0020619-3: RES, 1.0 k, 5%, 0.125 W, AEC-Q200 Grade 0, 0805; Manufacturer: Panasonic; Power_W: 125mW; TempCo: 200 ppm/C; Value_Code: 1k00; Value: 1.0k; EIA_Code: E24; Res_ohm: 1k; SizeX_mm: 2; SizeY_mm: 1.25; SizeZ_mm: 1.45; Value2: 0.125W; SizeArea_mm2: 2.5; AEC Qualified: Y; VDC_V: 150V; AEC Category: Q200; AEC Grade: 0; SizeAreaWB_mm2: 6.75
R2 R4 R7 R9 R12 R16 R19 = CMP-0018684-3: RES, 470 k, 5%, 0.25 W, AEC-Q200 Grade 0, 1206; Manufacturer: Vishay-Dale; Power_W: 250mW; TempCo: 200 ppm/C; Value: 470k; EIA_Code: E24; SizeX_mm: 3.2; SizeY_mm: 1.6; SizeZ_mm: 1.35; Value2: 0.25W; SizeArea_mm2: 5.12; AEC Qualified: Y; VDC_V: 200V; AEC Category: Q200; AEC Grade: 0
R3 R10 R15 = CMP-0020842-3: RES, 10.0 k, 1%, 0.125 W, AEC-Q200 Grade 0, 0805; Manufacturer: Vishay-Dale; Power_W: 125mW; TempCo: 100 ppm/C; Value_Code: 10k0; Value: 10.0k; EIA_Code: E96; Res_ohm: 10k; SizeX_mm: 2; SizeY_mm: 1.25; SizeZ_mm: 1.45; Value2: 0.125W; SizeArea_mm2: 2.5; AEC Qualified: Y; VDC_V: 150V; AEC Category: Q200; AEC Grade: 0
R5 R8 R13 R17 = CMP-0018610-3: RES, 1.0 M, 5%, 0.25 W, AEC-Q200 Grade 0, 1206; Manufacturer: Vishay-Dale; Power_W: 250mW; TempCo: 200 ppm/C; Value_Code: 1M00; Value: 1.0Meg; EIA_Code: E24; Res_ohm: 1M; SizeX_mm: 3.2; SizeY_mm: 1.6; SizeZ_mm: 1.35; Value2: 0.25W; SizeArea_mm2: 5.12; AEC Qualified: Y; VDC_V: 200V; AEC Category: Q200; AEC Grade: 0
R11 = CMP-0018578-3: RES, 10, 5%, 0.25 W, AEC-Q200 Grade 0, 1206; Manufacturer: Vishay-Dale; Power_W: 250mW; TempCo: 200 ppm/C; Value_Code: 10R0; Value: 10; EIA_Code: E24; SizeX_mm: 3.2; SizeY_mm: 1.6; SizeZ_mm: 1.35; Value2: 0.25W; SizeArea_mm2: 5.12; AEC Qualified: Y; VDC_V: 200V; AEC Category: Q200; AEC Grade: 0
R14 R18 = CMP-0018759-2: RES, 0, 5%, 0.25 W, 1206; Manufacturer: Yageo America; Power_W: 250mW; TempCo: 200 ppm/C; Value_Code: 0000; U/M: EA; Value: 0; EIA_Code: E24; SizeX_mm: 3.2; SizeY_mm: 1.6; SizeZ_mm: 1.35; Value2: 0.25W; SizeArea_mm2: 5.12; VDC_V: 200V; AEC Category: Q200
R20 R37 = CMP-0023153-5: RES, 4.70 k, 1%, 0.1 W, 0603; Manufacturer: Yageo; Power_W: 100mW; TempCo: 100 ppm/C; Value_Code: 4k70; Value: 4.70k; Res_ohm: 4.7k; SizeX_mm: 1.6; SizeY_mm: 0.8; SizeZ_mm: 1; Value2: 0.1W; SizeArea_mm2: 1.28; AEC Qualified: N; VDC_V: 75V; AEC Category: Q200; SizeAreaWB_mm2: 4.68
R22 = CMP-0022448-4: RES, 49.9, 1%, 0.1 W, AEC-Q200 Grade 0, 0603; Manufacturer: Vishay-Dale; Power_W: 100mW; TempCo: 100 ppm/C; Value_Code: 49R9; Value: 49.9; EIA_Code: E96; SizeX_mm: 1.6; SizeY_mm: 0.8; SizeZ_mm: 1; Value2: 0.1W; SizeArea_mm2: 1.28; AEC Qualified: Y; VDC_V: 75V; AEC Category: Q200; AEC Grade: 0
R23 = CMP-0018603-3: RES, 1.0 k, 5%, 0.25 W, AEC-Q200 Grade 0, 1206; Manufacturer: Vishay-Dale; Power_W: 250mW; TempCo: 200 ppm/C; Value_Code: 1k00; Value: 1.0k; EIA_Code: E24; Res_ohm: 1k; SizeX_mm: 3.2; SizeY_mm: 1.6; SizeZ_mm: 1.35; Value2: 0.25W; SizeArea_mm2: 5.12; AEC Qualified: Y; VDC_V: 200V; AEC Category: Q200; AEC Grade: 0
R24 = CMP-0020497-3: RES, 20, 5%, 0.125 W, AEC-Q200 Grade 0, 0805; Manufacturer: Vishay-Dale; Power_W: 125mW; TempCo: 200 ppm/C; Value_Code: 20R0; Value: 20; EIA_Code: E24; SizeX_mm: 2; SizeY_mm: 1.25; SizeZ_mm: 1.45; Value2: 0.125W; SizeArea_mm2: 2.5; AEC Qualified: Y; VDC_V: 150V; AEC Category: Q200; AEC Grade: 0
R25 = CMP-0022277-4: RES, 2.49 k, 1%, 0.1 W, AEC-Q200 Grade 0, 0603; Manufacturer: Vishay-Dale; Power_W: 100mW; TempCo: 100 ppm/C; Value_Code: 2k49; Value: 2.49k; EIA_Code: E96; SizeX_mm: 1.6; SizeY_mm: 0.8; SizeZ_mm: 1; Value2: 0.1W; SizeArea_mm2: 1.28; AEC Qualified: Y; VDC_V: 75V; AEC Category: Q200; AEC Grade: 0
R26 = CMP-0022563-4: RES, 6.81 k, 1%, 0.1 W, AEC-Q200 Grade 0, 0603; Manufacturer: Vishay-Dale; Power_W: 100mW; TempCo: 100 ppm/C; Value_Code: 6k81; Value: 6.81k; EIA_Code: E96; SizeX_mm: 1.6; SizeY_mm: 0.8; SizeZ_mm: 1; Value2: 0.1W; SizeArea_mm2: 1.28; AEC Qualified: Y; VDC_V: 75V; AEC Category: Q200; AEC Grade: 0
R27 R29 = CMP-0021759-3: RES, 60.4 k, 1%, 0.125 W, AEC-Q200 Grade 0, 0805; Manufacturer: Panasonic; Power_W: 125mW; TempCo: 100 ppm/C; Value_Code: 60k4; Value: 60.4k; EIA_Code: E96; SizeX_mm: 2; SizeY_mm: 1.25; SizeZ_mm: 1.45; Value2: 0.125W; SizeArea_mm2: 2.5; AEC Qualified: Y; AEC Category: Q200; AEC Grade: 0; SizeAreaWB_mm2: 6.75
R28 = CMP-0023066-5: RES, 38.3 k, 1%, 0.1 W, 0603; Manufacturer: Yageo; Power_W: 100mW; TempCo: 100 ppm/C; Value_Code: 38k3; Value: 38.3k; EIA_Code: E96; SizeX_mm: 1.6; SizeY_mm: 0.8; SizeZ_mm: 1; Value2: 0.1W; SizeArea_mm2: 1.28; AEC Qualified: N; VDC_V: 75V; AEC Category: Q200; SizeAreaWB_mm2: 4.68
R30 R33 = CMP-0022746-5: RES, 10.0 k, 1%, 0.1 W, 0603; Manufacturer: Yageo; Power_W: 100mW; TempCo: 100 ppm/C; Value_Code: 10k0; Value: 10.0k; EIA_Code: E96; Res_ohm: 10k; SizeX_mm: 1.6; SizeY_mm: 0.8; SizeZ_mm: 1; Value2: 0.1W; SizeArea_mm2: 1.28; AEC Qualified: N; VDC_V: 75V; AEC Category: Q200; SizeAreaWB_mm2: 4.68
R31 = CMP-0021990-4: RES, 100 k, 1%, 0.1 W, AEC-Q200 Grade 0, 0603; Manufacturer: Vishay-Dale; Power_W: 100mW; TempCo: 100 ppm/C; Value: 100k; EIA_Code: E96; SizeX_mm: 1.6; SizeY_mm: 0.8; SizeZ_mm: 1; Value2: 0.1W; SizeArea_mm2: 1.28; AEC Qualified: Y; VDC_V: 75V; AEC Category: Q200; AEC Grade: 0
R32 = CMP-0023036-5: RES, 33.2 k, 1%, 0.1 W, 0603; Manufacturer: Yageo; Power_W: 100mW; TempCo: 100 ppm/C; Value_Code: 33k2; Value: 33.2k; EIA_Code: E96; SizeX_mm: 1.6; SizeY_mm: 0.8; SizeZ_mm: 1; Value2: 0.1W; SizeArea_mm2: 1.28; AEC Qualified: N; VDC_V: 75V; AEC Category: Q200; SizeAreaWB_mm2: 4.68
R34 = CMP-0022109-5: RES, 1.00 k, 1%, 0.1 W, AEC-Q200 Grade 0, 0603; Manufacturer: Vishay-Dale; Power_W: 100mW; TempCo: 100 ppm/C; Value_Code: 1k00; Value: 1.00k; EIA_Code: E96; Res_ohm: 1k; SizeX_mm: 1.6; SizeY_mm: 0.8; SizeZ_mm: 1; Value2: 0.1W; SizeArea_mm2: 1.28; AEC Qualified: Y; VDC_V: 75V; AEC Category: Q200; AEC Grade: 0
R35 = CMP-0016530-2: RES, 0.5, 1%, 1 W, 2010; Manufacturer: Stackpole Electronics Inc; Power_W: 1W; TempCo: 250 ppm/C; Value_Code: R500; U/M: EA; Value: 0.5; SizeX_mm: 5; SizeY_mm: 2.5; SizeZ_mm: 1.66; SizeArea_mm2: 12.5; AEC Category: Q200
R36 = CMP-0023037-5: RES, 33.0 k, 1%, 0.1 W, 0603; Manufacturer: Yageo; Power_W: 100mW; TempCo: 100 ppm/C; Value_Code: 33k0; Value: 33.0k; Res_ohm: 33k; SizeX_mm: 1.6; SizeY_mm: 0.8; SizeZ_mm: 1; Value2: 0.1W; SizeArea_mm2: 1.28; AEC Qualified: N; VDC_V: 75V; AEC Category: Q200; SizeAreaWB_mm2: 4.68
RT1-RT3 = CMP-0002556-2: Thermistor NTC, 4.70 ohm, 20%, 8.5mm Disc; Manufacturer: TDK; TaMax_C: 170°C; TaMin_C: -55°C; Power_W: 1.4W; U/M: EA
T1 = CMP-0094994-1: TRANSFORMER; Manufacturer: Wurth; DCR_ohm: 0.87; Ns1toNp: 4.67:1/6:1/6:1/7:1/1:1; Ind_H: 700µH; Frequency_Fixed: 40kHz; AEC Qualified: No; Voltage_Isolation_Vrms: 500V; SizeZ_mm: 22.86mm
TP1-TP3 TP5 = CMP-0055149-2: Test Point, Multipurpose, White, TH; Manufacturer: Keystone Electronics; ContactFinish: Silver; CT: TRUE; CNHeader: FALSE; Green_Lifecycle: Active; Green_REACh: Passed
TP4 = CMP-0055147-2: Test Point, Multipurpose, Red, TH; Manufacturer: Keystone Electronics; CT: TRUE; ContactFinish: Silver; Green_Lifecycle: Active; CNHeader: FALSE; Green_REACh: Passed
TP6 = CMP-0055137-2: Test Point, Miniature, Red, TH; Manufacturer: Keystone Electronics; Green_REACh: Passed; Green_Lifecycle: Active; ContactFinish: Silver; CNHeader: FALSE; CT: TRUE
TP7 = CMP-0055140-2: Test Point, Miniature, Orange, TH; Manufacturer: Keystone Electronics; Green_Lifecycle: Active; ContactFinish: Silver; CNHeader: FALSE; CT: TRUE; Green_REACh: Passed
TP8 = CMP-0055148-2: Test Point, Multipurpose, Black, TH; Manufacturer: Keystone Electronics; CNHeader: FALSE; ContactFinish: Silver; Green_REACh: Passed; Green_Lifecycle: Active; CT: TRUE
TP9 = CMP-0055138-2: Test Point, Miniature, Black, TH; Manufacturer: Keystone Electronics; ContactFinish: Silver; CNHeader: FALSE; Green_Lifecycle: Active; Green_REACh: Passed; CT: TRUE
U1 = CMP-0013050-3: High-Frequency Multi-Mode Synchronous Rectifier Controller, DBV0005A (SOT-23-5); Manufacturer: Texas Instruments; Alternate PartNumber: UCC24612-1DBVT; SizeX_mm: 2.8; SizeY_mm: 2.9; CompType: IC; SizeZ_mm: 1.45; SizeArea_mm2: 8.12; SizeAreaWB_mm2: 14.82; AEC Category: Q200; AEC Qualified: N
U2 = CMP-0006181-3: Optocoupler, 5 kV, 80-160% CTR, SMT; Manufacturer: Fairchild Semiconductor; PartNumber: FOD817ASD; CTR (Max): 160%; CTR (Min): 80%; Voltage_Isolation_Vrms: 5kV
U3 = CMP-0078369-2: High-Efficiency Low-Cost Flyback Controller with Secondary-Side Regulation, DBV0006A (SOT-23-6); Manufacturer: Texas Instruments; SizeZ_mm: 1.45; SizeX_mm: 2.8; SizeY_mm: 2.9; AEC Category: Q200; AEC Qualified: N; SizeArea_mm2: 8.12; CompType: IC; SizeAreaWB_mm2: 14.82
U4 = CMP-0033091-1: Adjustable Precision Shunt Regulator, 34 ppm / degC, 100 mA, -40 to 85 degC, 3-pin SOT-23 (DBZ), Green (RoHS & no Sb/Br); Manufacturer: Texas Instruments; Temp Coeff(Typ)(ppm/ degree C): 34; SubFamily: Shunt Voltage Reference; Min Iz for Regulation(uA): 600; Iout/Iz(Max)(mA): 100; VO Adj(Min)(V): 2.495; Rating: Catalog; VO Adj(Max)(V): 36; Temp Coeff(Max)(ppm/ degree C): 92; Initial Accuracy @ 25/deg C(%): 1

## Sheet TIDA-010239_PWR_Backup.SchDoc
size 431 x 279 mm; Date: Not shown in title block; ApprovedBy: Not shown in title block; CheckedBy: Not shown in title block; Author: Not shown in title block; CompanyName: Not shown in title block; Engineer: Not shown in title block; Organization: Not shown in title block; Address1: Not shown in title block; Address2: Not shown in title block; Address3: Not shown in title block; Address4: Not shown in title block; DocumentNumber: 2; Revision: Use project parameter SCH_Rev; SheetNumber: 3; SheetTotal: 9; PageSetup: Record=PageOptions¦CenterHorizontal=True¦CenterVertical=True¦PrintScale=1.00¦XCorrection=1.00¦YCorrection=1.00¦PrintKind=0¦BorderSize=5000000¦LeftOffset=0¦BottomOffset=0¦Orientation=2¦PaperLength=1000¦PaperWidth=1000¦Scale=100¦PaperSource=15¦PrintQuality=600¦MediaType=1¦DitherType=10¦PaperKind=Letter¦PrintScaleMode=1
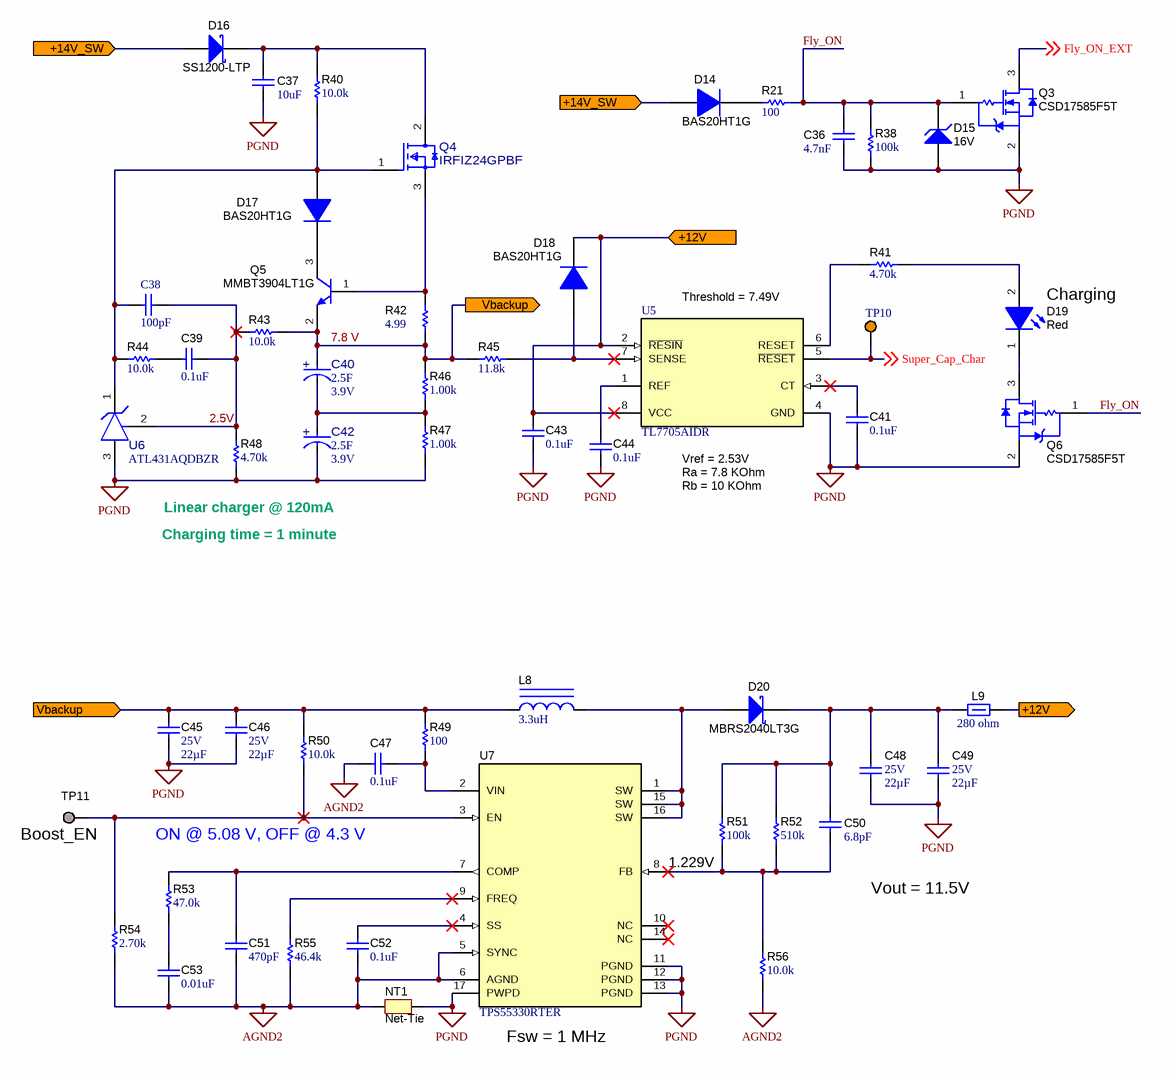
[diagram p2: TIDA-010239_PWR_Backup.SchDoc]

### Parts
C36  Cap_F: 4.7nF  [0603]  (hidden comment: 885012206087)
C37  ValueDisplayed: 10uF  [1206_180]  (hidden comment: CL31B106KBHNNNE)
C38  value 100pF  [WCAP-CSGP_0603_L1.6W0.8H0.8_Reflow]  (hidden comment: 885012006057)
C39  value 0.1uF  [0603]  (hidden comment: C1608X7R1H104K080AA)
C40  VDC_V: 3.9V  ValueDisplayed: 2.5F  [FP-PHVL-3R9V255-R_RADIAL-MFG]  (hidden comment: PHVL-3R9V255-R)
C41  value 0.1uF  [0603]  (hidden comment: C1608X7R1H104K080AA)
C42  VDC_V: 3.9V  ValueDisplayed: 2.5F  [FP-PHVL-3R9V255-R_RADIAL-MFG]  (hidden comment: PHVL-3R9V255-R)
C43  value 0.1uF  [0603]  (hidden comment: C1608X7R1H104K080AA)
C44  value 0.1uF  [0603]  (hidden comment: C1608X7R1H104K080AA)
C45  VDC_V: 25V  ValueDisplayed: 22µF  [1210_270]  (hidden comment: CC1210KKX7R8BB226)
C46  VDC_V: 25V  ValueDisplayed: 22µF  [1210_270]  (hidden comment: CC1210KKX7R8BB226)
C47  value 0.1uF  [0603]  (hidden comment: C1608X7R1H104K080AA)
C48  VDC_V: 25V  ValueDisplayed: 22µF  [1210_270]  (hidden comment: CC1210KKX7R8BB226)
C49  VDC_V: 25V  ValueDisplayed: 22µF  [1210_270]  (hidden comment: CC1210KKX7R8BB226)
C50  ValueDisplayed: 6.8pF  [0603]  (hidden comment: CC0603CRNPO0BN6R8)
C51  Cap_F: 470pF  [0603]  (hidden comment: 885012206081)
C52  value 0.1uF  [0603]  (hidden comment: C1608X7R1H104K080AA)
C53  value 0.01uF  [0603]  (hidden comment: C0603C103K5RACTU)
D14  BAS20HT1G  [SOD-323]
D15  value 16V  [SOD-323]  (hidden comment: SZMM3Z16VST1G)
D16  SS1200-LTP  [SMA]
D17  BAS20HT1G  [SOD-323]
D18  BAS20HT1G  [SOD-323]
D19  value Red  [WL_SMCW_RED_1206]  (hidden comment: 150120RS75000)
D20  MBRS2040LT3G  [SMB]
L8  ValueDisplayed: 3.3uH  [XEL4030_310]  (hidden comment: XEL4030-332MEB)
L9  value 280 ohm  [1206]  (hidden comment: 74279221281)
NT1  Net-Tie  [Net-Tie_0805_HV_NoOverlay]  (net tie, no BOM)
Q3  CSD17585F5T  [YJK0003A]
Q4  IRFIZ24GPBF  [FP-IRFIZ24GPBF_TO-220-3-MFG]
Q5  MMBT3904LT1G  [SOT-23]
Q6  CSD17585F5T  [YJK0003A]
R21  ValueDisplayed: 100  [0805_HV]  (hidden comment: CRCW0805100RFKEA)
R38  ValueDisplayed: 100k  [0603]  (hidden comment: CRCW0603100KFKEA)
R40  ValueDisplayed: 10.0k  [0603]  (hidden comment: RC0603FR-0710KL)
R41  ValueDisplayed: 4.70k  [0603]  (hidden comment: RC0603FR-074K7L)
R42  ValueDisplayed: 4.99  [0603]  (hidden comment: CRCW06034R99FKEA)
R43  ValueDisplayed: 10.0k  [0603]  (hidden comment: RC0603FR-0710KL)
R44  ValueDisplayed: 10.0k  [0603]  (hidden comment: RC0603FR-0710KL)
R45  ValueDisplayed: 11.8k  [0603]  (hidden comment: RC0603FR-0711K8L)
R46  ValueDisplayed: 1.00k  [0603]  (hidden comment: CRCW06031K00FKEA)
R47  ValueDisplayed: 1.00k  [0603]  (hidden comment: CRCW06031K00FKEA)
R48  ValueDisplayed: 4.70k  [0603]  (hidden comment: RC0603FR-074K7L)
R49  ValueDisplayed: 100  [0603]  (hidden comment: CRCW0603100RFKEA)
R50  ValueDisplayed: 10.0k  [0603]  (hidden comment: RC0603FR-0710KL)
R51  ValueDisplayed: 100k  [0603]  (hidden comment: CRCW0603100KFKEA)
R52  ValueDisplayed: 510k  [0603]  (hidden comment: RC0603FR-07510KL)
R53  ValueDisplayed: 47.0k  [0603]  (hidden comment: RC0603FR-0747KL)
R54  ValueDisplayed: 2.70k  [0603]  (hidden comment: RC0603FR-072K7L)
R55  ValueDisplayed: 46.4k  [0603]  (hidden comment: RT0603DRE0746K4L)
R56  ValueDisplayed: 10.0k  [0603]  (hidden comment: RC0603FR-0710KL)
TP10  5003  [Keystone5003]  (value not drawn)
TP11  TP_SM_1MM  [TP_SM_1MM]  (value not drawn)  (no BOM)
U5  TL7705AIDR  [D0008A_N]
U6  ATL431AQDBZR  [DBZ0003A-MFG]
U7  TPS55330RTER  [RTE0016C_NV]

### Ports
+12V (in), +12V (out), +14V_SW (in), Vbackup (in), Vbackup (out)

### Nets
AGND2: C47.1 C51.2 C52.2 C53.1 NT1.1 R54.1 R55.1 R56.1 U7.5(SYNC) U7.6(AGND)
PGND: C36.2 C37.2 C41.2 C42.1(CATHODE) C43.2 C44.2 C45.1 C46.1 C48.1 C49.1 D15.2(A) NT1.2 Q3.2(S) Q6.2(S) R38.1 R47.1 R48.1 U5.4(GND) U6.3(ANODE) U7.11(PGND) U7.12(PGND) U7.13(PGND) U7.17(PWPD)
+12V: C43.1 D18.1(K) L9.2 U5.2(~{RESIN}) U5.8(VCC) ; port +12V
+14V_SW: D14.2(A) D16.2(A) ; port +14V_SW
Fly_ON: C36.1 D15.1(K) Q3.1(G) Q6.1(G) R21.2 R38.2
Fly_ON_EXT: Q3.3(D) ; off-sheet Fly_ON_EXT
Super_Cap_Char: TP10.1 U5.5(~{RESET}) ; off-sheet Super_Cap_Char
Vbackup: C40.2(ANODE) C45.2 C46.2 L8.1 Q5.2(E) R42.1 R43.1 R45.1 R46.2 R49.2 R50.2 ; port Vbackup
NetC37_1: C37.1 D16.1(K) Q4.2(D) R40.1
NetC38_1: C38.1 D17.2(A) Q4.1(G) R40.2 R44.1 U6.1(CATHODE)
NetC38_2: C38.2 C39.2 R43.2 R48.2 U6.2(REF)
NetC39_1: C39.1 R44.2
NetC40_1: C40.1(CATHODE) C42.2(ANODE) R46.1 R47.2
NetC41_1: C41.1 U5.3(CT)
NetC44_1: C44.1 U5.1(REF)
NetC47_2: C47.2 R49.1 U7.2(VIN)
NetC48_2: C48.2 C49.2 C50.1 D20.1(K) L9.1 R51.2 R52.2
NetC50_2: C50.2 R51.1 R52.1 R56.2 U7.8(FB)
NetC51_1: C51.1 R53.2 U7.7(COMP)
NetC52_1: C52.1 U7.4(SS)
NetC53_2: C53.2 R53.1
NetD14_1: D14.1(K) R21.1
NetD17_1: D17.1(K) Q5.3(C)
NetD18_2: D18.2(A) R45.2 U5.7(SENSE)
NetD19_1: D19.1(K) Q6.3(D)
NetD19_2: D19.2(A) R41.1
NetD20_2: D20.2(A) L8.2 U7.1(SW) U7.15(SW) U7.16(SW)
NetQ4_3: Q4.3(S) Q5.1(B) R42.2
NetR41_2: R41.2 U5.6(RESET)
NetR50_1: R50.1 R54.2 TP11.1 U7.3(EN)
NetR55_2: R55.2 U7.9(FREQ)

Not connected (* = marked no-connect by the designer): U7 10(NC)* 14(NC)*

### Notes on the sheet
- (near U5) Threshold = 7.49V
- (near D19) Charging
- 7.8 V
- (near R48) 2.5V
- (near U5) Vref = 2.53V
- (near R48) Linear charger @ 120mA
- Charging time = 1 minute
- Ra = 7.8 KOhm
- Rb = 10 KOhm
- (near TP11) Boost_EN
- ON @ 5.08 V, OFF @ 4.3 V
- (near R51) 1.229V
- Vout = 11.5V
- (near U7) Fsw = 1 MHz

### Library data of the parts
C36 = CMP-0006835-4: CAP, CERM, 4700 pF, 50 V, +/- 10%, X7R, 0603; Manufacturer: Wurth Elektronik; TaMin_C: -55°C; Polarized: N; SizeAreaWB_mm2: 4.68; Value1: Unknown; U/M: EA; Value: 4700pF; TaMax_C: 125°C; SizeZ_mm: 1; SizeX_mm: 1.6; SizeY_mm: 0.8; Value2: 50V; SizeArea_mm2: 1.28; AEC Category: Q200
C37 = CMP-0008802-2: CAP, CERM, 10 uF, 50 V, +/- 10%, X7R, 1206; Manufacturer: Samsung; TaMin_C: -55°C; Polarized: N; SizeAreaWB_mm2: 10.92; Value1: Unknown; U/M: EA; Value: 10uF; TaMax_C: 125°C; SizeZ_mm: 1.8; SizeX_mm: 3.2; SizeY_mm: 1.6; Cap_Case: 1206; Value2: 50V; SizeArea_mm2: 5.12; Cap_F: 10µF; AEC Category: Q200
C38 = CMP-0118889-1: as C33 on sheet TIDA-010239_PWR_Flyback
C39 C41 C43 C44 C47 C52 = CMP-0007044-5: as C18 on sheet TIDA-010239_PWR_Flyback
C40 C42 = CMP-0095175-1: 2.5 F (EDLC) Supercapacitor 3.9 V Radial 80mOhm 5000 Hrs @ 85°C; Manufacturer: Cooper Bussmann; SizeZ_mm: 23.5mm; Value: 2.5F; AEC Qualified: No; Tolerance_%: 30%
C45 C46 C48 C49 = CMP-0082267-1: as C5 on sheet TIDA-010239_PWR_Flyback
C50 = CMP-0084374-1: CAP, CERM, 6.8 pF, 100 V,+/- 3.7%, C0G/NP0, 0603; Manufacturer: Yageo; TaMin_C: -55°C; Value: 6.8pF; SizeArea_mm2: 1.28; Polarized: N; VDC_V: 100V; TaMax_C: 125°C; SizeZ_mm: 1; U/M: EA; SizeY_mm: 0.8; SizeAreaWB_mm2: 4.68; SizeX_mm: 1.6; AEC Category: Q200
C51 = CMP-0006834-5: CAP, CERM, 470 pF, 50 V, +/- 10%, X7R, 0603; Manufacturer: Wurth Elektronik; TaMin_C: -55°C; Polarized: N; SizeAreaWB_mm2: 4.68; Value1: Unknown; U/M: EA; Value: 470pF; TaMax_C: 125°C; SizeZ_mm: 1; SizeX_mm: 1.6; SizeY_mm: 0.8; Value2: 50V; SizeArea_mm2: 1.28; AEC Category: Q200
C53 = CMP-0006854-4: CAP, CERM, 0.01 uF, 50 V, +/- 10%, X7R, 0603; Manufacturer: Kemet; TaMin_C: -55°C; Polarized: N; SizeAreaWB_mm2: 4.68; Value1: Unknown; U/M: EA; TaMax_C: 125°C; SizeZ_mm: 1; SizeX_mm: 1.6; SizeY_mm: 0.8; Value2: 50V; SizeArea_mm2: 1.28; Cap_F: 10nF; AEC Category: Q200
D14 D17 D18 = CMP-0029150-2: as D12 on sheet TIDA-010239_PWR_Flyback
D15 = CMP-0085763-1: Diode, Zener, 16 V, 300 mW, AEC-Q101, SOD-323; Manufacturer: ON Semiconductor; Power_W: 300mW; AEC Category: Q101; Value1: 0.3W; SizeZ_mm: 1; SizeX_mm: 2.7; RJA_CperW: 416; SizeArea_mm2: 3.645; AEC Qualified: Y; SizeY_mm: 1.35; SizeAreaWB_mm2: 8.695
D16 = CMP-0028981-2: as D1 on sheet TIDA-010239_PWR_Flyback
D19 = CMP-0002935-3: as D9 on sheet TIDA-010239_PWR_Flyback
D20 = CMP-0028529-2: Diode, Schottky, 40 V, 2 A, SMB; Manufacturer: ON Semiconductor; TJmax_C: 125°C; AEC Category: Q101; SizeY_mm: 3.81; Io_A: 2A; SizeX_mm: 5.6; Vf_V: 430mV; RJC_CperW: 22.5; Vr_V: 40V; SizeAreaWB_mm2: 44.156; SizeZ_mm: 2.6; Green_Lifecycle: Active; SizeArea_mm2: 21.336; Value2: 0.43V; Value: 40V; Green_REACh: Passed
L8 = CMP-0061090-1: Inductor, Shielded, 3.3 uH, 5 A, 0.0286 ohm, SMD; Manufacturer: Coilcraft; Isat: 5.9A @ 30% inductance drop; Irms: 5A @ 20C rise; SizeAreaWB_mm2: 25; DCR_ohm: 28.6m; Value: 3.3uH; Imax_A: 5A; SizeZ_mm: 3.1; SizeX_mm: 4; SizeArea_mm2: 16; Ind_H: 3.3µH; AEC Qualified: N; AEC Category: Q200
L9 = CMP-0003140-1: Ferrite Bead, 280 ohm @ 100 MHz, 3.5 A, 1206; Manufacturer: Wurth Elektronik; Ztyp@1GHz_Ohm: 79.415; ZTyp@100MHz_Ohm: 280; SizeAreaWB_mm2: 10.92; DCR_ohm: 22m; Value1: 0.022 ohm; Imax_A: 3.5A; SizeZ_mm: 1.35; SizeX_mm: 3.2; SizeY_mm: 1.6; SizeArea_mm2: 5.12
NT1 = CMP-0078142-6: Single point connection between nets.
Q3 Q6 = CMP-0067551-1: MOSFET, N-CH, 30 V, 5.9 A, YJK0003A (PICOSTAR-3); Alternate Manufacturer: None; Manufacturer: Texas Instruments; Rdson45_ohm: 0.033; QgTyp_nC: 1.9; SizeAreaWB_mm2: 4.3077; Vgs_V: 20V; Value1: 0.033 ohm; VdsMax_V: 30V; U/M: EA; Value: 30V; IdsMax_A: 5.9A; SizeZ_mm: 0.35; SizeX_mm: 1.49; SizeY_mm: 0.73; Value2: 1.9 nC; SizeArea_mm2: 1.0877; ChType: N; AEC Category: Q101
Q4 = CMP-0124068-1: N-Channel 60 V 14A (Tc) 37W (Tc) Through Hole TO-220-3; Manufacturer: Vishay; AEC Qualified: No; QgTyp_nC: 25nC @ 10V; Rdson45_ohm: 0.1; SizeZ_mm: 19.62mm; VdsMax_V: 1.5V; Vgs_V: 20V; Drain To Source Breakdown Voltage: 60V; Input Capacitance At Vds: 640pF @ 25V; Number Of Channels: 1; Pulse Drain Current: 56A; Reverse Recovery Charge: 320nC; Reverse Recovery Time: 90ns; Rthja Max: 65°C/W; Standoff Height: 3.1mm; Threshold Vgs Max: 4V; Threshold Vgs Min: 2V; TJmax_C: +175°C; Turn Off Delay Time: 25ns; Turn On Delay Time: 13ns
Q5 = CMP-0000419-2: Transistor, NPN, 40 V, 0.2 A, SOT-23; Manufacturer: ON Semiconductor; TaMax_C: 150°C; Value2: 300; Value1: 0.2 A; Vcesat1_V: 300mV; SizeX_mm: 2.5; SizeY_mm: 3; TaMin_C: -55°C; IcRated_A: 200mA; CompType: BJT; SizeZ_mm: 1.1; Value: 40 V; SizeArea_mm2: 7.5; NPN: 1; Vceo_V: 40V; PNP: 0; AEC Category: Q101; SizeAreaWB_mm2: 14; U/M: EA
R21 = CMP-0020835-3: RES, 100, 1%, 0.125 W, AEC-Q200 Grade 0, 0805; Manufacturer: Vishay-Dale; Power_W: 125mW; TempCo: 100 ppm/C; Value_Code: 100R; Value: 100; EIA_Code: E96; SizeX_mm: 2; SizeY_mm: 1.25; SizeZ_mm: 1.45; Value2: 0.125W; SizeArea_mm2: 2.5; AEC Qualified: Y; VDC_V: 150V; AEC Category: Q200; AEC Grade: 0
R38 R51 = CMP-0021990-4: as R31 on sheet TIDA-010239_PWR_Flyback
R40 R43 R44 R50 R56 = CMP-0022746-5: as R30 on sheet TIDA-010239_PWR_Flyback
R41 R48 = CMP-0023153-5: as R20 on sheet TIDA-010239_PWR_Flyback
R42 = CMP-0022478-4: RES, 4.99, 1%, 0.1 W, AEC-Q200 Grade 0, 0603; Manufacturer: Vishay-Dale; Power_W: 100mW; TempCo: 100 ppm/C; Value_Code: 4R99; Value: 4.99; EIA_Code: E96; SizeX_mm: 1.6; SizeY_mm: 0.8; SizeZ_mm: 1; Value2: 0.1W; SizeArea_mm2: 1.28; AEC Qualified: Y; VDC_V: 75V; AEC Category: Q200; AEC Grade: 0
R45 = CMP-0022762-5: RES, 11.8 k, 1%, 0.1 W, 0603; Manufacturer: Yageo; Power_W: 100mW; TempCo: 100 ppm/C; Value_Code: 11k8; Value: 11.8k; EIA_Code: E96; SizeX_mm: 1.6; SizeY_mm: 0.8; SizeZ_mm: 1; Value2: 0.1W; SizeArea_mm2: 1.28; AEC Qualified: N; VDC_V: 75V; AEC Category: Q200; SizeAreaWB_mm2: 4.68
R46 R47 = CMP-0022109-5: as R34 on sheet TIDA-010239_PWR_Flyback
R49 = CMP-0021991-4: RES, 100, 1%, 0.1 W, AEC-Q200 Grade 0, 0603; Manufacturer: Vishay-Dale; Power_W: 100mW; TempCo: 100 ppm/C; Value_Code: 100R; Value: 100; EIA_Code: E96; SizeX_mm: 1.6; SizeY_mm: 0.8; SizeZ_mm: 1; Value2: 0.1W; SizeArea_mm2: 1.28; AEC Qualified: Y; VDC_V: 75V; AEC Category: Q200; AEC Grade: 0
R52 = CMP-0023162-4: RES, 510 k, 1%, 0.1 W, 0603; Manufacturer: Yageo; Power_W: 100mW; TempCo: 100 ppm/C; Value: 510k; SizeX_mm: 1.6; SizeY_mm: 0.8; SizeZ_mm: 1; Value2: 0.1W; SizeArea_mm2: 1.28; AEC Qualified: N; VDC_V: 75V; AEC Category: Q200; SizeAreaWB_mm2: 4.68
R53 = CMP-0023133-5: RES, 47.0 k, 1%, 0.1 W, 0603; Manufacturer: Yageo; Power_W: 100mW; TempCo: 100 ppm/C; Value_Code: 47k0; Value: 47.0k; Res_ohm: 47k; SizeX_mm: 1.6; SizeY_mm: 0.8; SizeZ_mm: 1; Value2: 0.1W; SizeArea_mm2: 1.28; AEC Qualified: N; VDC_V: 75V; AEC Category: Q200; SizeAreaWB_mm2: 4.68
R54 = CMP-0022996-5: RES, 2.70 k, 1%, 0.1 W, 0603; Manufacturer: Yageo; Power_W: 100mW; TempCo: 100 ppm/C; Value_Code: 2k70; Value: 2.70k; Res_ohm: 2.7k; SizeX_mm: 1.6; SizeY_mm: 0.8; SizeZ_mm: 1; Value2: 0.1W; SizeArea_mm2: 1.28; AEC Qualified: N; VDC_V: 75V; AEC Category: Q200; SizeAreaWB_mm2: 4.68
R55 = CMP-0025309-3: RES, 46.4 k, 0.5%, 0.1 W, 0603; Manufacturer: Yageo America; Power_W: 100mW; TempCo: 50 ppm/C; Value_Code: 46k4; U/M: EA; Value: 46.4k; EIA_Code: E192; SizeX_mm: 1.6; SizeY_mm: 0.8; SizeZ_mm: 1; Value2: 0.1W; SizeArea_mm2: 1.28; VDC_V: 75V; AEC Category: Q200
TP10 = CMP-0055140-2: Test Point, Miniature, Orange, TH; Manufacturer: Keystone Electronics; CNHeader: FALSE; Green_Lifecycle: Active; Green_REACh: Passed; ContactFinish: Silver; CT: TRUE
TP11 = CMP-0003825-1: 1mm Test Point, SMT; Manufacturer: Any
U5 = CMP-0032057-1: Single Supply Voltage Supervisor for 5 V Systems with Programmable Time Delay, 1 Supply Monitored, -40 to 85 degC, 8-pin SOIC (D), Green (RoHS & no Sb/Br); Manufacturer: Texas Instruments; Threshold Voltage 1 (typ)(Typ)(V): 4.55; Output Driver Type / Reset Output: Active-low, Open-drain, Active-high, Open-drain; VCC(Min)(V): 3.5; # of Supplies Monitored: 1; VCC(Max)(V): 18; Rating: Catalog; SubFamily: Supervisor and Reset IC; Iq(Typ)(uA): 1800; Reset Threshold Accuracy(%): 1.1
U6 = CMP-0124349-2: V-Ref Adjustable/Precision 2.5V to 36V 100mA 3-Pin SOT-23 T/R; Manufacturer: Texas Instruments; SizeZ_mm: 1.12mm; AEC Qualified: No; Number Of Outputs: 1; Output Type: AdjustableProgrammable; Output Voltage: 2.5-36V; Reference Type: Shunt; Standoff Height: 0.01mm; TaMax_C: +125°C; TaMin_C: -40°C; TJmax_C: +150°C; AEC Category: Q200; CompType: IC
U7 = CMP-0067160-2: Integrated 5-A 24-V Wide Input Range Boost/SEPIC/Flyback DC-DC Regulator, RTE0016C (WQFN-16); Alternate PartNumber: TPS55330RTET; Manufacturer: Texas Instruments; SizeZ_mm: 0.8; SizeX_mm: 3.0; SizeArea_mm2: 9.0; CompType: IC; U/M: EA; SizeAreaWB_mm2: 16.0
